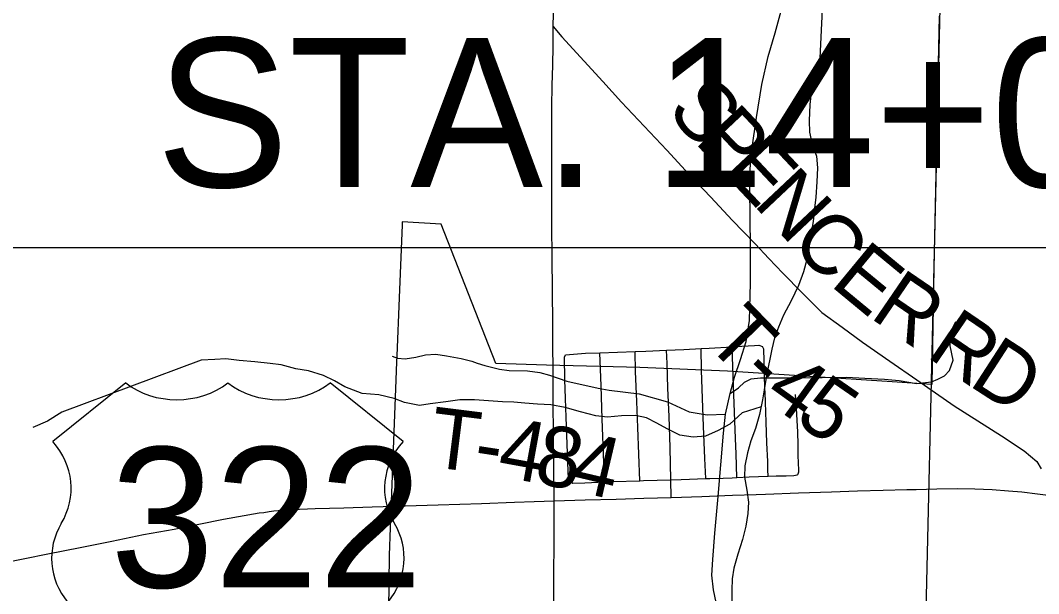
# Model space of a CAD drawing. Extents: x -6.1 to 38, y -7.7 to 22.
# Drawn here: x 7.096 to 8.054, y 16.867 to 17.406 of the extents above; entities that cross this region are included whole.
import ezdxf

# ---------------------------------------------------------------- set-up
doc = ezdxf.new("R2010")
doc.units = 0
for name, color, linetype in [('GM_X_City_Street', 7, 'Continuous'), ('GM_X_Corporation', 7, 'Continuous'), ('GM_X_County_Road', 7, 'Continuous'), ('GM_X_Minor_River', 7, 'Continuous'), ('GM_X_Township_Road', 7, 'Continuous'), ('GM_X_Township_Road_Text', 7, 'Continuous'), ('GM_X_US_Location', 7, 'Continuous'), ('GM_X_US_Route', 7, 'Continuous'), ('GM_X_US_Shield', 7, 'Continuous'), ('SH_Text', 7, 'Continuous')]:
    doc.layers.add(name, color=color, linetype=linetype)

msp = doc.modelspace()

# ---------------------------------------------------------------- linework, layer by layer
at = {"layer": 'GM_X_City_Street'}
msp.add_lwpolyline([(7.76791, 17.07023), (7.7738, 17.087), (7.77902, 17.10377), (7.78207, 17.12358), (7.78295, 17.15865), (7.78295, 17.18674), (7.78273, 17.22594), (7.78207, 17.25904), (7.78425, 17.28408), (7.78861, 17.31456), (7.79383, 17.34571), (7.79971, 17.37183), (7.80624, 17.39405), (7.81191, 17.41495)], dxfattribs=at)
at = {"layer": 'GM_X_Corporation'}
for points in [[(6.8881, 19.93659), (7.17492, 19.92346), (7.23616, 19.921), (8.02661, 19.88922), (8.02125, 19.70471), (8.02079, 19.68982), (8.0189, 19.62846), (7.99279, 18.77986), (7.97287, 17.92154), (7.97183, 17.87641), (7.95308, 17.06692), (7.95307, 17.06643), (7.93594, 16.3267), (7.92512, 16.10977), (7.91657, 15.91251), (7.90988, 15.74002), (7.90533, 15.62285), (7.88899, 15.0865), (7.88923, 14.89059), (7.27984, 14.90301), (6.7864, 14.92029)], [(7.96058, 17.40979), (7.95566, 17.17268), (7.95358, 17.06363), (7.91651, 17.06604), (7.76155, 17.07614), (7.67898, 17.07942), (7.59109, 17.08174), (7.54356, 17.08324), (7.49198, 17.21422), (7.4553, 17.2164), (7.45519, 17.21371), (7.45248, 17.14512), (7.45032, 17.09052), (7.44993, 17.0848), (7.44928, 17.06786), (7.44394, 16.92876), (7.44295, 16.90286), (7.44139, 16.77262)]]:
    msp.add_lwpolyline(points, dxfattribs=at)
msp.add_lwpolyline([(8.9, 14.85918), (8.9, 19.87135), (8.53815, 19.88018), (8.02661, 19.88922), (8.02125, 19.70471), (8.02079, 19.68982), (8.0189, 19.62846), (7.99279, 18.77986), (7.97287, 17.92154), (7.97183, 17.87641), (7.95308, 17.06692), (7.95307, 17.06643), (7.93594, 16.3267), (7.92512, 16.10977), (7.91657, 15.91251), (7.90988, 15.74002), (7.90533, 15.62285), (7.88899, 15.0865), (7.88923, 14.89059), (8.1023, 14.88375), (8.27757, 14.87811), (8.6137, 14.86789)], close=True, dxfattribs=at)
at = {"layer": 'GM_X_County_Road'}
msp.add_line((7.59797, 16.82426), (7.59819, 16.95416), dxfattribs=at)
for points in [[(7.59734, 17.40008), (7.59813, 17.42433)], [(7.59819, 16.95416), (7.59796, 16.98523), (7.59773, 17.0163), (7.5975, 17.04737), (7.59727, 17.07844), (7.59711, 17.09957), (7.59695, 17.12069), (7.59671, 17.15176), (7.59648, 17.18283), (7.59625, 17.21288), (7.59602, 17.24293), (7.59618, 17.32426), (7.59638, 17.345), (7.59696, 17.3635), (7.59754, 17.382), (7.59734, 17.40008)]]:
    msp.add_lwpolyline(points, dxfattribs=at)
at = {"layer": 'GM_X_Minor_River'}
for points in [[(7.85184, 17.44268), (7.84793, 17.36382), (7.84267, 17.35054), (7.84043, 17.34068), (7.83897, 17.32665), (7.83825, 17.31149), (7.83867, 17.30088), (7.84097, 17.28913), (7.84517, 17.27815), (7.84596, 17.26716), (7.84562, 17.25389), (7.84453, 17.23948), (7.84343, 17.22925), (7.84195, 17.21711), (7.83824, 17.1936), (7.83601, 17.18109), (7.83303, 17.16933), (7.82815, 17.15643), (7.82139, 17.14201), (7.81425, 17.12872), (7.80936, 17.11734), (7.80561, 17.10747), (7.803, 17.09685), (7.80114, 17.08737), (7.79854, 17.07372), (7.79594, 17.05855), (7.79445, 17.04907), (7.79147, 17.03542), (7.78773, 17.02214), (7.78323, 17.01038), (7.78024, 16.99938), (7.77763, 16.98686), (7.77729, 16.97624), (7.77959, 16.96412), (7.78114, 16.95275), (7.78042, 16.94214), (7.77856, 16.93038), (7.77557, 16.91787), (7.77108, 16.90383), (7.76734, 16.89093), (7.76586, 16.8807), (7.76552, 16.87008), (7.76555, 16.85757)], [(7.79303, 17.04256), (7.77521, 17.03689), (7.76352, 17.02624), (7.75257, 17.02015), (7.74087, 17.01481), (7.72915, 17.01403), (7.71666, 17.01589), (7.70454, 17.02192), (7.69507, 17.02721), (7.68523, 17.03211), (7.67501, 17.03436), (7.66178, 17.03394), (7.64855, 17.03277), (7.63758, 17.03388), (7.6232, 17.03763), (7.60882, 17.04177), (7.5952, 17.04438), (7.58272, 17.04511), (7.57061, 17.04583), (7.5604, 17.04694), (7.54981, 17.04729), (7.52334, 17.04912), (7.50972, 17.04908), (7.49649, 17.04715), (7.48175, 17.04521), (7.47155, 17.04367), (7.45755, 17.04666), (7.4477, 17.05043), (7.43332, 17.0538), (7.41782, 17.05489), (7.40153, 17.06129), (7.39168, 17.06695), (7.38146, 17.07185), (7.36707, 17.07636), (7.35535, 17.07822), (7.34134, 17.08197), (7.33113, 17.08308), (7.31675, 17.08493), (7.302, 17.08603), (7.28952, 17.08751), (7.27893, 17.0871), (7.26608, 17.0863), (7.135, 17.0374), (7.12179, 17.02903), (7.10782, 17.02292)]]:
    msp.add_lwpolyline(points, dxfattribs=at)
at = {"layer": 'GM_X_Township_Road'}
for p, q in [((7.76378, 17.05499), (7.76791, 17.07023)), ((7.75946, 17.03574), (7.76378, 17.05499)), ((7.8264, 17.04124), (7.82537, 17.05408))]:
    msp.add_line(p, q, dxfattribs=at)
for points in [[(7.59734, 17.40008), (7.60548, 17.39042), (7.62645, 17.36749), (7.64404, 17.34824), (7.66165, 17.32898), (7.68292, 17.30634), (7.7042, 17.2837), (7.72548, 17.26105), (7.74566, 17.23956), (7.76585, 17.21807), (7.78731, 17.1956), (7.80034, 17.18195), (7.81338, 17.16831), (7.83171, 17.14977), (7.85005, 17.13124), (7.86929, 17.11724), (7.88854, 17.10324), (7.91403, 17.08549), (7.93953, 17.06774), (7.9571, 17.05551), (7.97466, 17.04328), (7.99688, 17.0293), (8.0191, 17.01533), (8.04068, 17.00103), (8.05236, 16.99097), (8.05662, 16.98428)], [(7.89056, 17.06935), (7.90916, 17.06838), (7.92279, 17.06721), (7.93937, 17.06441), (7.95328, 17.06589), (7.95944, 17.06838), (7.96551, 17.07165), (7.97018, 17.07655), (7.97368, 17.08635), (7.97088, 17.09989), (7.97111, 17.11273), (7.97625, 17.12277)], [(7.44606, 17.08997), (7.45103, 17.08822), (7.45819, 17.08763), (7.4683, 17.08932), (7.47744, 17.09148), (7.48706, 17.09196), (7.49692, 17.09052), (7.51087, 17.08787), (7.52073, 17.08546), (7.52579, 17.08354), (7.533, 17.08138), (7.54696, 17.07801), (7.5561, 17.07656), (7.57317, 17.07632), (7.58496, 17.07464), (7.59389, 17.07235), (7.61024, 17.06651), (7.63988, 17.05998), (7.65011, 17.05826), (7.67839, 17.05461), (7.705, 17.04714), (7.72539, 17.03779), (7.74239, 17.03486), (7.75946, 17.03574)], [(7.60916, 17.09137), (7.62793, 17.09291), (7.64143, 17.09338), (7.65791, 17.09394), (7.6744, 17.0945), (7.68473, 17.09485), (7.70411, 17.09576), (7.72034, 17.09652), (7.73657, 17.09729), (7.74405, 17.09764), (7.76585, 17.09896), (7.76908, 17.09914), (7.78689, 17.10021), (7.79082, 17.1004), (7.79433, 17.09909)], [(7.64568, 16.97182), (7.64474, 16.9982), (7.64411, 17.01469), (7.64348, 17.03118), (7.64245, 17.06223), (7.64194, 17.07781), (7.64143, 17.09338)], [(7.67884, 16.973), (7.67791, 16.99795), (7.67698, 17.02319), (7.67599, 17.04753), (7.67496, 17.07583), (7.6744, 17.0945)], [(7.70847, 16.95726), (7.70813, 16.97389), (7.70738, 17.00409), (7.7065, 17.03326), (7.70537, 17.06016), (7.70477, 17.08307), (7.70411, 17.09576)], [(7.74091, 16.97506), (7.74016, 16.9938), (7.73885, 17.0242), (7.73796, 17.05035), (7.73708, 17.07687), (7.73657, 17.09729)], [(7.77034, 16.97602), (7.76964, 16.99826), (7.76903, 17.01274), (7.768, 17.03746), (7.76697, 17.06217), (7.76641, 17.08056), (7.76585, 17.09896)], [(7.79957, 16.9774), (7.79934, 16.98313), (7.79924, 16.99105), (7.79854, 17.00873), (7.7977, 17.0281), (7.79705, 17.04674), (7.79672, 17.0559), (7.79658, 17.05961), (7.79626, 17.07225), (7.79588, 17.08583), (7.79556, 17.09683), (7.79433, 17.09909)], [(7.6136, 16.97238), (7.61171, 16.97519), (7.61157, 16.98209), (7.61058, 17.0074), (7.6096, 17.03271), (7.60892, 17.05041), (7.60825, 17.06811), (7.60793, 17.08908), (7.60916, 17.09137)], [(7.76378, 17.05499), (7.77184, 17.06043), (7.7775, 17.06566), (7.78382, 17.06871), (7.79238, 17.0697), (7.82768, 17.06981), (7.87339, 17.07025), (7.89056, 17.06935)], [(7.75071, 16.85857), (7.7481, 16.87033), (7.74679, 16.88405), (7.74766, 16.89907), (7.74963, 16.92368), (7.75267, 16.95809), (7.75768, 17.01775), (7.75946, 17.03574)], [(7.82803, 16.97952), (7.82834, 16.98044), (7.82847, 16.98139), (7.82858, 16.9828), (7.82806, 16.99687), (7.82778, 17.00667), (7.82745, 17.01887), (7.82713, 17.02978), (7.8264, 17.04124)], [(7.6136, 16.97238), (7.61592, 16.97076), (7.62715, 16.97106), (7.64568, 16.97182), (7.65354, 16.97214), (7.67884, 16.973), (7.68254, 16.97313), (7.70813, 16.97389), (7.71775, 16.97417), (7.74091, 16.97506), (7.74484, 16.9752), (7.75735, 16.9755), (7.76593, 16.97581), (7.77034, 16.97602), (7.78175, 16.97657), (7.79048, 16.97702), (7.79957, 16.9774), (7.80725, 16.97758), (7.81658, 16.97769), (7.82399, 16.97782), (7.82704, 16.97843), (7.8277, 16.97898), (7.82803, 16.97952)]]:
    msp.add_lwpolyline(points, dxfattribs=at)
at = {"layer": 'GM_X_US_Route'}
for points in [[(7.07857, 16.89542), (7.1003, 16.89978), (7.12204, 16.90414), (7.1525, 16.9103), (7.18216, 16.91631), (7.21183, 16.92232), (7.24077, 16.9276), (7.26408, 16.93227), (7.28738, 16.93695), (7.30668, 16.9403), (7.31532, 16.94202), (7.3207, 16.94284), (7.32506, 16.94324), (7.33015, 16.94406), (7.33471, 16.94456), (7.33868, 16.94497), (7.34304, 16.94527), (7.35137, 16.94588), (7.37341, 16.9468), (7.40032, 16.94755), (7.42724, 16.94832), (7.45829, 16.9493), (7.48934, 16.95028), (7.50973, 16.95093), (7.53012, 16.95157), (7.56117, 16.95275), (7.57968, 16.95346), (7.59819, 16.95416), (7.62743, 16.9549), (7.65667, 16.95563), (7.68257, 16.95645), (7.70847, 16.95726), (7.73736, 16.95832), (7.76626, 16.95939), (7.78829, 16.96015)], [(7.78829, 16.96015), (7.79731, 16.96046), (7.82836, 16.96153), (7.85941, 16.9626), (7.88362, 16.96344), (7.90783, 16.96427), (7.93016, 16.96472)], [(7.93016, 16.96472), (7.9389, 16.9649), (7.95841, 16.96529), (7.97791, 16.96569), (7.99411, 16.96523), (8.01031, 16.96477), (8.02575, 16.96345), (8.03834, 16.96254), (8.05307, 16.96061), (8.06302, 16.95929)]]:
    msp.add_lwpolyline(points, dxfattribs=at)
at = {"layer": 'GM_X_US_Shield'}
for p, q in [((7.19521, 17.06489), (7.12655, 17.00996)), ((7.45614, 17.00996), (7.38747, 17.06489))]:
    msp.add_line(p, q, dxfattribs=at)
for centre, major_axis, start_param, end_param in [((7.24328, 17.10412), (-0.06866, 0), 0.795399, 2.346194), ((7.33941, 17.10412), (-0.06866, 0), 0.795399, 2.346194), ((7.0478, 16.96585), (0.09613, 0), 5.838949, 6.894067), ((7.53488, 16.96585), (-0.09613, 0), 5.672304, 6.727422), ((7.22161, 16.90009), (0.09613, 0), 2.702327, 4.723529), ((7.36108, 16.90009), (-0.09613, 0), 1.559657, 3.580859)]:
    msp.add_ellipse(centre, major_axis=major_axis, ratio=0.8, start_param=start_param, end_param=end_param, dxfattribs=at)
at = {"layer": 'SH_Text'}
msp.add_lwpolyline([(7.00018, 17.85635), (8.83305, 17.85635), (8.83305, 17.19187), (7.00018, 17.19187)], close=True, dxfattribs=at)

# ---------------------------------------------------------------- texts
at = {"layer": 'GM_X_Township_Road_Text'}
for s, rotation, p in [('S', 313.26939, (7.7031, 17.31979)), ('P', 313.26613, (7.72937, 17.29188)), ('E', 313.27156, (7.75565, 17.26396)), ('N', 313.26102, (7.78478, 17.23302)), ('C', 313.45748, (7.81919, 17.19645)), ('E', 320.46385, (7.85683, 17.1574)), ('R', 325.63545, (7.89409, 17.12699)), ('T', 314.08178, (7.73887, 17.10394)), ('R', 325.69421, (7.94718, 17.09062)), ('D', 327.075, (7.98697, 17.06349)), ('-', 316.88364, (7.7706, 17.07129)), ('4', 324.2269, (7.79376, 17.0503)), ('5', 325.38467, (7.82318, 17.02912)), ('T', 352.87605, (7.47916, 16.98638)), ('4', 349.68212, (7.54357, 16.9777)), ('8', 349.01462, (7.57783, 16.97146)), ('-', 351.28589, (7.52092, 16.98116)), ('4', 346.76902, (7.61161, 16.96492))]:
    msp.add_text(s, height=0.05682, rotation=rotation, dxfattribs=at).set_placement(p)
at = {"layer": 'GM_X_US_Location'}
for s, p in [('0', (7.29144, 16.93845)), ('/', (7.29146, 16.93845))]:
    msp.add_text(s, height=0.000189, dxfattribs=at).set_placement(p)
msp.add_text('322', height=0.000189, rotation=0.00001, dxfattribs=at).set_placement((7.23318, 16.89925))
at = {"layer": 'GM_X_US_Shield'}
msp.add_text('322', height=0.131836, dxfattribs=at).set_placement((7.18055, 16.87263))
at = {"layer": 'SH_Text'}
msp.add_text('STA. 14+05.00', height=0.1399997, dxfattribs=at).set_placement((7.22378, 17.2492))

doc.saveas('drawing.dxf')
